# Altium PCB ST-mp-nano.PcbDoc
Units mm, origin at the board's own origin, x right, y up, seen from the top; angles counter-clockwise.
Board outline 18.67 x 47.4 mm, 2 copper layers (Top Layer, Bottom Layer); 49 components, 54 nets, 204 pads, 46 vias.
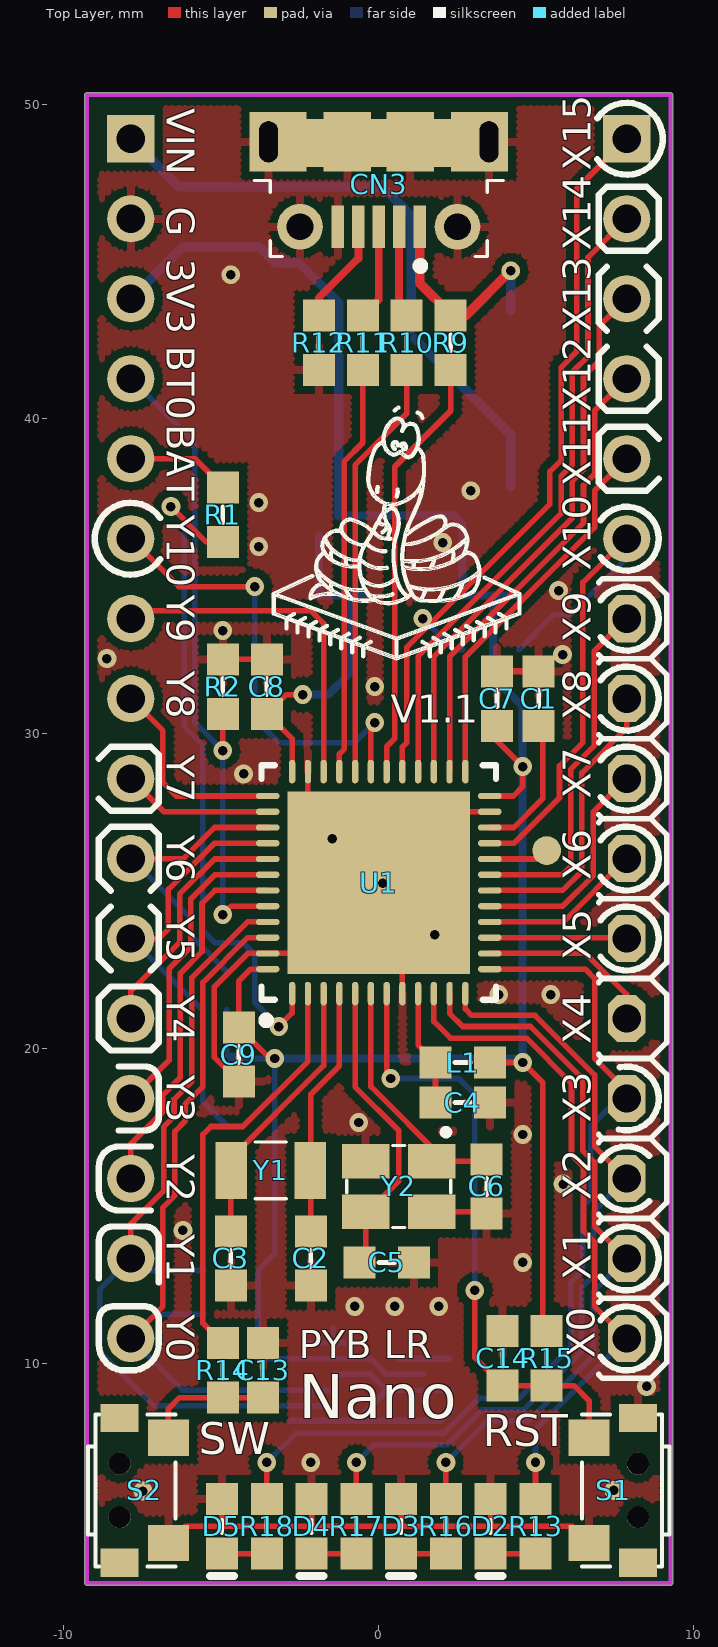
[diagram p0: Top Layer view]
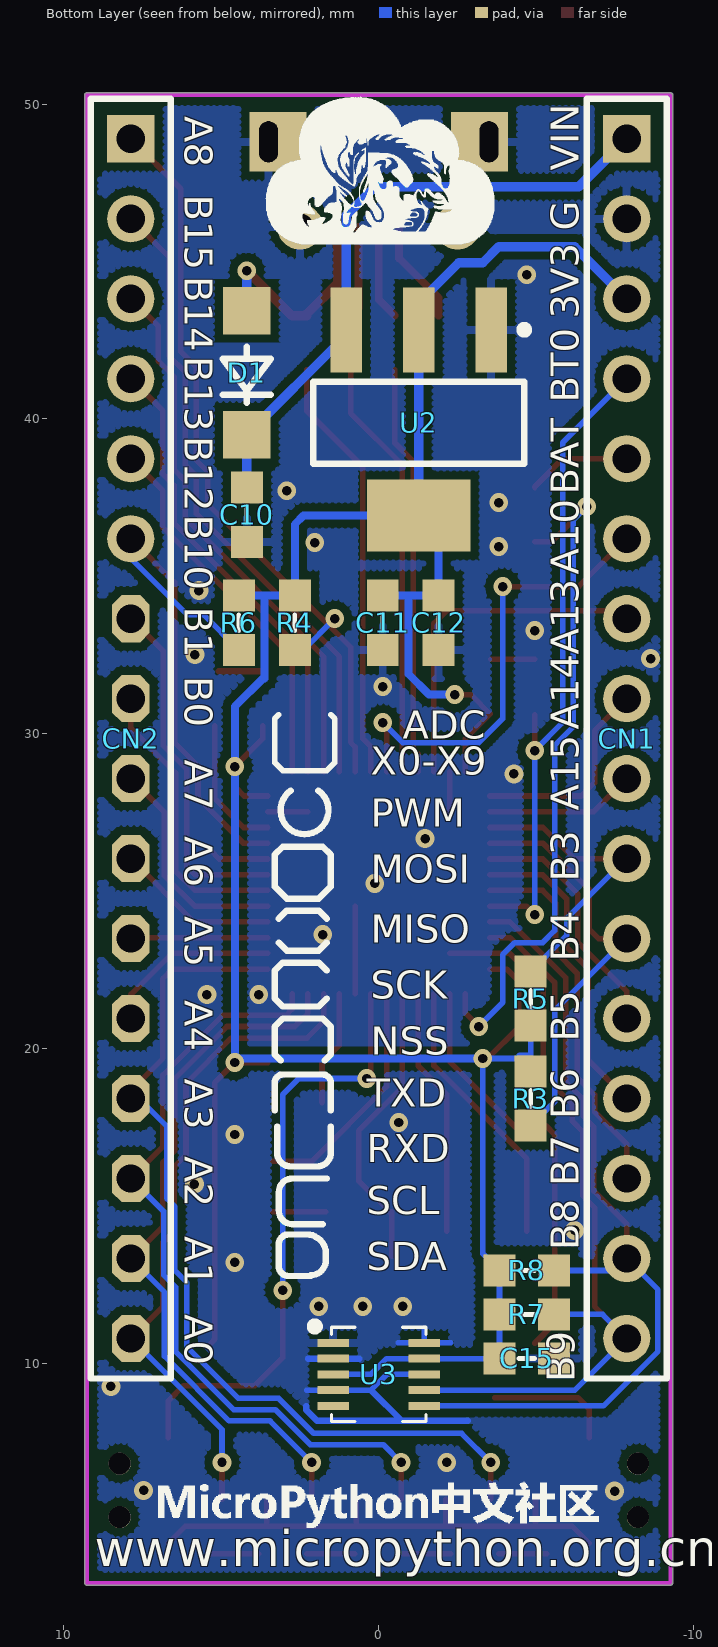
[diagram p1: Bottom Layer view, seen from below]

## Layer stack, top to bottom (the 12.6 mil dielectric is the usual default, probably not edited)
Top Layer: signal copper 0.0356
Dielectric: dielectric 0.32, FR-4, Dk 4.8
Bottom Layer: signal copper 0.0356

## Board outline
-9.335,3.023 ccw(c-9.271,3.023) -9.271,2.959 9.271,2.959 ccw(c9.271,3.023) 9.335,3.023 9.335,50.292 ccw(c9.271,50.292) 9.271,50.356 -9.271,50.356 ccw(c-9.271,50.292) -9.335,50.292

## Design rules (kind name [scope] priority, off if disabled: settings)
Clearance Clearance_polygon [InPolygon] p1: gap=0.254
Clearance [All] p2: gap=0.152
DiffPairsRouting [All] p1: maxlimit=0.254 minlimit=0.178 mostfreqgap=0.178 maxuncoupledlength=12.7
HoleSize [All] p1: absolutevalues=TRUE maxlimit=5.08 minlimit=0.025 maxpercent=80.000 minpercent=20.000
HoleToHoleClearance [All] p1: gap=0.178 allowstackedmicrovias=TRUE
MinimumSolderMaskSliver [All] p1: minsoldermaskwidth=0.178
PolygonConnect PolygonConnect_via [IsVia] p1: connectstyle=Direct reliefconductorwidth=0.254 reliefentries=4 polygonreliefangle="90 Angle"
PolygonConnect [All] p2: connectstyle=Relief reliefconductorwidth=0.254 reliefentries=4 polygonreliefangle="90 Angle"
RoutingVias [All] p1: holewidth=0.4 width=0.8 viastyle="Through Hole" minholewidth=0.3 minwidth=0.6 maxholewidth=0.711 maxwidth=1.27
SilkToSilkClearance [All] p1: silktosilkclearance=0.178
SilkscreenOverComponentPads [All] p1: minsilkscreentomaskgap=0.178
SolderMaskExpansion [All] p1: expansion=0.102
Width [All] p1: maxlimit=0.508 minlimit=0.178 preferedwidth=0.178
22 further rules are at their usual default settings.

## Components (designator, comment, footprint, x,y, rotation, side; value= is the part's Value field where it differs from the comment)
C1 "2u2" SMD0603 5.08,31.115 r90 top
C2 "2.2p" SMD0603 -2.159,13.335 r90 top
C3 "2.2p" SMD0603 -4.699,13.335 r90 top
C4 "104" SMD0603 2.667,18.288 r180 top
C5 "18p" SMD0603 0.254,13.208 r0 top
C6 "18p" SMD0603 3.429,15.621 r270 top
C7 "2u2" SMD0603 3.759,31.115 r90 top
C8 "104" SMD0603 -3.556,31.496 r270 top
C9 "104" SMD0603 -4.445,19.812 r90 top
C10 "2u2" SMD0603 4.191,36.957 r90 bottom
C11 "2u2" SMD0603 -0.127,33.528 r90 bottom
C12 "104" SMD0603 -1.905,33.528 r90 bottom
C13 "104" SMD0603 -3.683,9.779 r270 top
C14 "104" SMD0603 3.937,10.16 r270 top
C15 "104" SMD0603 -4.699,10.16 r0 bottom
CN1 "Header 16" HDR1X16#1 -7.874,48.895 r270 bottom
CN2 "Header 16" HDR1X16#2 7.874,48.895 r270 bottom
CN3 "1050170001" MOLEX_1050170001 0,46.101 r180 top locked
D1 "SS14" "SS24 - small" 4.191,43.434 r270 bottom
D2 "LED RED" LED0603 3.556,4.826 r90 top
D3 "LED GREEN" LED0603 0.711,4.826 r90 top
D4 "LED Yellow" LED0603 -2.134,4.826 r90 top
D5 "LED Blue" LED0603 -4.978,4.826 r90 top
L1 "1uH" SMD0603 2.667,19.558 r180 top
R1 "220" SMD0603 -4.953,36.957 r270 top
R2 "100k" SMD0603 -4.953,31.496 r90 top
R3 "10k" SMD0603 -4.826,18.415 r270 bottom
R4 "10k" SMD0603 2.667,33.528 r270 bottom
R5 "10k" SMD0603 -4.826,21.59 r90 bottom
R6 "10k" SMD0603 4.445,33.528 r270 bottom
R7 "10k" SMD0603 -4.699,11.557 r180 bottom
R8 "10k" SMD0603 -4.699,12.954 r180 bottom
R9 "560" SMD0603 2.286,42.418 r90 top
R10 "22R" SMD0603 0.889,42.418 r90 top
R11 "22R" SMD0603 -0.508,42.418 r90 top
R12 "100k" SMD0603 -1.905,42.418 r90 top
R13 "560" SMD0603 4.978,4.826 r270 top
R14 "10k" SMD0603 -4.953,9.779 r90 top
R15 "10k" SMD0603 5.334,10.16 r90 top
R16 "560" SMD0603 2.134,4.826 r270 top
R17 "560" SMD0603 -0.711,4.826 r270 top
R18 "560" SMD0603 -3.556,4.826 r270 top
S1 "SW-RST" SWPB_2X4_L 8.23,5.969 r270 top
S2 "" SWPB_2X4_L -8.23,5.969 r90 top
U1 "STM32F401CEU6" QFN48 0,25.273 r90 top
U2 "LM1117" SOT223 -1.27,39.878 r0 bottom
U3 "MMA7660FC" MMA7660 0,9.652 r180 bottom
Y1 "32K" TXC_9H03200019 -3.429,16.129 r180 top
Y2 "8M" SMD3225 0.635,15.621 r180 top

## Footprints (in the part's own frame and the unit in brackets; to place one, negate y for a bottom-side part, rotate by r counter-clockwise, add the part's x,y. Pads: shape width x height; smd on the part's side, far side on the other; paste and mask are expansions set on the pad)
HDR1X16#1 [mm] "Connector; Header; 16 Position"
  rect 1.5x1.5 hole 0.9: 1(0,0)
  round 1.5 hole 0.9: 2(2.54,0) 3(5.08,0) 4(7.62,0) 5(10.16,0) 6(12.7,0) 7(15.24,0) 8(17.78,0) 9(20.32,0) 10(22.86,0) 11(25.4,0) 12(27.94,0) 13(30.48,0) 14(33.02,0) 15(35.56,0) 16(38.1,0)
  silkscreen extent -1.27,-1.27 39.37,1.27
HDR1X16#2 [mm] "Connector; Header; 16 Position"
  rect 1.5x1.5 hole 0.9: 1(0,0)
  round 1.5 hole 0.9: 2(2.54,0) 3(5.08,0) 4(7.62,0) 5(10.16,0) 6(12.7,0)
  oct 1.5x1.2 hole 0.9: 7(15.24,0) 8(17.78,0) 9(20.32,0) 10(22.86,0) 11(25.4,0) 12(27.94,0) 13(30.48,0) 14(33.02,0) 15(35.56,0) 16(38.1,0)
  silkscreen extent -1.27,-1.27 39.37,1.27
LED0603 [mil]
  rect 40x40 smd: 1(-34,0) 2(34,0)
  silkscreen extent -62,-15 8,15
MMA7660 [mm]
  rect 1x0.25 smd: 1(-1.45,1) 2(-1.45,0.5) 3(-1.45,0) 4(-1.45,-0.5) 5(-1.45,-1) 6(1.45,-1) 7(1.45,-0.5) 8(1.45,0) 9(1.45,0.5) 10(1.45,1)
  silkscreen extent -2.16,-1.5 1.5,1.65, body extent -1.52,-1.52 1.52,1.52, height 0.9
MOLEX_1050170001 [mm] "USB Micro-B Connector"
  rect 0.4x1.35 smd: 1(-1.3,0) 2(-0.65,0) 3(0,0) 4(0.65,0) 5(1.3,0)
  round 1.45 hole 0.85: 6(-2.5,0) 11(2.5,0)
  rect 1.8x1.9 hole 0.6 slot 1.3 at 90 deg copper offset 0.3,0: 7(-3.5,-2.7)
  rect 1.5x1.9 smd: 8(-1,-2.7) 9(1,-2.7)
  rect 1.8x1.9 hole 0.6 slot 1.3 at 90 deg copper offset -0.3,0: 10(3.5,-2.7)
  silkscreen extent -3.95,-1.46 3.95,1.37, body extent -4.1,-5.21 4.1,0.19, height 2.58
QFN48 [mm] "QFN, 48-Leads, Body 7x7mm, Pitch 0.5mm, IPC Medium Density"
  oval 0.75x0.2 smd: 1(-3.525,2.75) 2(-3.525,2.25) 3(-3.525,1.75) 4(-3.525,1.25) 5(-3.525,0.75) 6(-3.525,0.25) 7(-3.525,-0.25) 8(-3.525,-0.75) 9(-3.525,-1.25) 10(-3.525,-1.75) 11(-3.525,-2.25) 12(-3.525,-2.75) 25(3.525,-2.75) 26(3.525,-2.25) 27(3.525,-1.75) 28(3.525,-1.25) 29(3.525,-0.75) 30(3.525,-0.25) 31(3.525,0.25) 32(3.525,0.75) 33(3.525,1.25) 34(3.525,1.75) 35(3.525,2.25) 36(3.525,2.75)
  oval 0.2x0.75 smd: 13(-2.75,-3.525) 14(-2.25,-3.525) 15(-1.75,-3.525) 16(-1.25,-3.525) 17(-0.75,-3.525) 18(-0.25,-3.525) 19(0.25,-3.525) 20(0.75,-3.525) 21(1.25,-3.525) 22(1.75,-3.525) 23(2.25,-3.525) 24(2.75,-3.525) 37(2.75,3.525) 38(2.25,3.525) 39(1.75,3.525) 40(1.25,3.525) 41(0.75,3.525) 42(0.25,3.525) 43(-0.25,3.525) 44(-0.75,3.525) 45(-1.25,3.525) 46(-1.75,3.525) 47(-2.25,3.525) 48(-2.75,3.525)
  rect 5.8x5.8 smd: 49(0,0)
  silkscreen extent -4.5,-3.72 3.72,3.73, body extent -3.57,-3.57 3.57,3.57, height 0.9
SMD0603 [mil]
  rect 40x40 smd: 1(-34,0) 2(34,0)
  silkscreen extent -10,0 10,0, body extent -40,-20 40,20, height 20
SMD3225 [mm] "Crystal SMD 3.2x2.5mm compatible with 2.5x2.0mm"
  rect 1.5x1.1 smd mask+0.05: 1(-1.05,-0.8) 2(1.05,-0.8) 3(1.05,0.8) 4(-1.05,0.8)
  silkscreen extent -1.65,-1.82 1.65,1.3, body extent -1.65,-1.3 1.65,1.3, height 1
SOT223 [mm] "SOT223, 4-Leads, Body 6.5x3.5mm, Pitch 2.3mm, Lead Span 7mm, IPC Low Density"
  rect 1x2.7 smd: 1(-2.3,-2.95) 2(0,-2.95) 3(2.3,-2.95)
  rect 3.3x2.294 smd: 4(0,2.95)
  silkscreen extent -3.47,-3.07 3.35,1.3, body extent -3.35,-1.85 3.35,1.85, height 1.7
"SS24 - small" [mm]
  rect 1.5x1.5 smd: 1(0,0) 2(3.937,0)
  silkscreen extent 1.14,-0.76 2.92,0.76, body extent -0.64,-0.89 4.57,0.89, height 3
SWPB_2X4_L [mm]
  rect 1.15x1.3 smd: 1(-1.675,-1.55) 2(1.675,-1.55)
  rect 0.9x1.2 smd: ""(-2.3,0) ""(2.3,0)
  round 0.7 hole 0.7: ""(-0.85,0) ""(0.85,0)
  silkscreen extent -2.41,-1.78 2.41,1
TXC_9H03200019 [mm]
  rect 1x1.8 smd: 1(-1.25,0) 2(1.25,0)
  silkscreen extent -0.5,-0.9 0.5,0.9, body extent -1.73,-0.85 1.73,0.85, height 0.8

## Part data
C1 C2 C3 C4 C5 C6 C7 C8 C9 C10 C11 C12 C13 C14 C15: library part Cap
CN1 CN2: "Header, 16-Pin"
D1: library part Diode
D2: library part LED-RED
D3: library part LED-GREEN
D4: library part LED-YELLOW
D5: library part LED-BLUE
L1: library part Inductor
R1 R2 R3 R4 R5 R6 R7 R8 R9 R10 R11 R12 R13 R14 R15 R16 R17 R18: library part Res
S1 S2: library part SW-PB, "Switch"
U3: library part MMA7660
Y1: library part XTAL
Y2: library part XTAL_SMD

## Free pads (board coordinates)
  rect 5.08x1.524 smd: 0(0.229,48.768)
  round 0.914 smd: 0(5.334,26.289)

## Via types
v1: diameter 0.6, hole 0.3, Top Layer to Bottom Layer, 46 vias

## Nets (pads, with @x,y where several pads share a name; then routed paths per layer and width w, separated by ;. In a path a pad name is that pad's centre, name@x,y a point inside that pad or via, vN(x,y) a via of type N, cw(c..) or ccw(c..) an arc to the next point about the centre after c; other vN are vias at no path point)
BOOT0: CN1.4 R2.1 U1.44 | length 20.9
  Top Layer w0.178: v1(-4.953,24.257) -4.687,24.523 U1.44 ; v1(-4.953,29.464) R2.1@-4.953,30.607
  Bottom Layer w0.178: CN1.4 -5.842,39.243 -5.842,30.353 v1(-4.953,29.464) v1(-4.953,24.257)
DM: CN3.2 R10.2 | length 2.9
  Top Layer w0.254: CN3.2 0.65,43.521 R10.2
DP: CN3.3 R11.2 | length 3
  Top Layer w0.254: R11.2 0,43.79 CN3.3
GND: C1.2 C2.1 C3.1 C4.1 C5.2 C6.2 C7.2 C8.1 C9.1 C10.1 C11.1 C12.1 C13.1 C14.1 C15.1 CN1.2 CN3.5 CN3.6 CN3.7 CN3.8 CN3.9 CN3.10 CN3.11 D2.2 D3.2 D4.2 D5.2 pad.0@0.229,48.768 R2.2 R12.1 S1.2 S1.@8.23,8.269 S2.1 U1.8 U1.23 U1.35 U1.47 U1.49 U2.1 U3.1 U3.2 U3.4 U3.8 U3.10 Y2.2 Y2.4 | length 48.2
  Top Layer w0.178: S2.1 -6.148,4.826 3.556,4.826 ; -4.978,4.851 D5.2 ; R2.2 C8.1 ; C9.1 -5.22,19.723 -5.22,21.963 -4.16,23.023 U1.47 U1.49@-2.25,23.023 ; U1.49@-2.25,27.523 U1.35 ; -2.134,4.851 D4.2 ; 0.711,4.877 D3.2 ; U1.8 U1.49@0.75,24.523 ; Y2.4 C6.2@3.365,14.821 ; U1.49@2.25,27.523 U1.23 ; D2.2 3.556,4.826 ; S1.2 6.148,4.826 3.556,4.826
  Top Layer w0.203: C7.2@3.683,31.979 C1.2
  Bottom Layer w0.178: -2.286,10.652 U3.10 ; U3.8 -0.254,9.652 0.246,9.152 U3.4 2.286,9.152 ; -1.45,11.109 U3.10 ; -0.614,10.652 U3.10
  Bottom Layer w0.203: -2.831,8.179 -0.727,8.179 ; 0.246,9.152 -0.727,8.179 ; 0.614,10.152 U3.2 2.247,10.152 ; 2.306,8.649 2.306,8.523 1.961,8.179 -0.727,8.179
  other v1: -7.493,5.944 7.468,5.969 -2.159,6.858 8.509,9.271 -0.762,11.811 0.508,11.811 1.905,11.811 4.572,13.208 -6.223,14.224 5.854,15.697 4.572,17.272 -0.635,17.653 3.81,21.717 5.461,21.717 1.778,23.622 0.127,25.248 -1.473,26.67 -4.293,28.727 -0.127,31.496 -8.636,32.385 5.842,32.512 -4.953,33.274 5.715,34.544 -3.81,35.941 2.032,36.068 -3.81,37.338 2.921,37.719 -4.699,44.577
ID: CN3.4 R12.2 | length 3.3
  Top Layer w0.254: R12.2 -1.905,43.845 -0.65,45.1 CN3.4
NetC1_1: C1.1 U1.22 | length 4.4
  Top Layer w0.178: U1.22 4.29,27.023 5.207,27.94 C1.1@5.207,30.251
NetC2_2: C2.2 U1.4 Y1.1 | length 7.9
  Top Layer w0.178: C2.2 -2.159,18.547 -1.25,19.456 U1.4
NetC3_2: C3.2 U1.3 Y1.2 | length 8.8
  Top Layer w0.178: C3.2 -4.699,16.51 -1.75,19.459 U1.3
NetC4_2: C4.2 L1.2 U1.9 | length 3.7
  Top Layer w0.178: U1.9 1.25,20.111 L1.2 C4.2
NetC5_1: C5.1 U1.5 Y2.3 | length 9.4
  Top Layer w0.178: U1.5 -0.75,18.784 0.635,17.399 0.635,15.794 -0.338,14.821 Y2.3 C5.1@-0.415,13.403
NetC6_1: C6.1 U1.6 Y2.1 | length 7.6
  Top Layer w0.178: U1.6 -0.25,18.792 2.121,16.421 C6.1@3.365,16.421
NetC13_2: C13.2 R14.1 S2.2 | length 4.1
  Top Layer w0.178: S2.2 -6.68,8.56 -6.325,8.915 C13.2
NetD2_1: D2.1 R13.2 | length 1.5
  Top Layer w0.178: D2.1@3.81,3.962 R13.2@5.334,3.962
NetD3_1: D3.1 R16.2 | length 1.5
  Top Layer w0.178: D3.1@0.762,3.962 R16.2@2.286,3.962
NetD4_1: D4.1 R17.2 | length 1.5
  Top Layer w0.178: D4.1@-2.286,3.962 R17.2@-0.762,3.962
NetD5_1: D5.1 R18.2 | length 1.5
  Top Layer w0.178: D5.1@-5.334,3.962 R18.2@-3.81,3.962
NetR1_2: R1.2 U1.1 | length 21.8
  Top Layer w0.178: v1(-6.604,37.211) -5.486,36.093 R1.2 ; v1(-3.175,20.701) -2.75,21.126 U1.1
  Bottom Layer w0.178: v1(-6.604,37.211) -6.172,36.779 -6.172,30.216 -5.588,29.632 -5.588,23.749 -5.207,23.368 -4.318,23.368 -3.937,22.987 -3.937,21.463 v1(-3.175,20.701)
NRST: C14.2 R15.1 S1.1 U1.7 | length 19.4
  Top Layer w0.178: U1.7 0.25,19.181 v1(0.381,19.05) ; v1(3.048,12.319) 3.048,10.185 C14.2 R15.1 6.198,9.296 6.68,8.814 S1.1
  Bottom Layer w0.178: v1(0.381,19.05) 2.54,19.05 3.048,18.542 v1(3.048,12.319)
PA0: CN2.16 R13.1 U1.10 | length 21.2
  Top Layer w0.178: U1.10 1.75,20.856 2.273,20.333 4.686,20.333 6.121,18.898 6.121,16.617 6.502,16.236 6.502,14.204 6.857,13.849 6.857,11.812 CN2.16 ; R13.1 v1(4.978,6.858)
  Bottom Layer w0.178: v1(4.978,6.858) 4.978,7.899 CN2.16
PA1: CN2.15 R16.1 U1.11 | length 22.8
  Top Layer w0.178: R16.1 v1(2.134,6.858) ; U1.11 2.25,21.118 2.667,20.701 4.821,20.701 6.477,19.045 6.477,16.764 6.857,16.384 6.857,14.352 CN2.15
  Bottom Layer w0.178: v1(2.134,6.858) 3.454,8.179 4.755,8.179 6.807,10.231 6.807,12.268 CN2.15
PA2-TX2: CN2.14 R17.1 U1.12 | length 25.1
  Top Layer w0.178: R17.1 v1(-0.711,6.858) ; U1.12 2.75,21.253 2.946,21.057 4.968,21.057 6.858,19.167 6.858,18.837 ; 6.857,18.836 6.857,16.892 CN2.14
  Bottom Layer w0.178: v1(-0.711,6.858) -0.145,7.425 2.177,7.425 3.286,8.534 4.608,8.534 6.452,10.378 6.452,12.426 6.833,12.807 6.833,14.834 CN2.14
PA3-RX2: CN2.13 R18.1 U1.13 | length 28.8
  Top Layer w0.178: R18.1 v1(-3.556,6.858) ; U1.13 6.56,22.523 6.857,22.226 6.857,19.686 7.874,18.669 CN2.13
  Bottom Layer w0.178: v1(-3.556,6.858) -2.634,7.78 2.065,7.78 3.175,8.89 4.46,8.89 6.096,10.526 6.096,12.573 6.477,12.954 6.477,14.986 6.731,15.24 6.731,17.526 7.62,18.415 CN2.13
PA4-NSS1: CN2.12 U1.14 | length 5.7
  Top Layer w0.178: U1.14 6.568,23.023 7.874,21.717 CN2.12
PA5-SCK1: CN2.11 U1.15 | length 4.3
  Top Layer w0.178: U1.15 CN2.11@7.846,23.523
PA6-MISO1: CN2.10 U1.16 | length 5.2
  Top Layer w0.178: U1.16 5.862,24.023 CN2.10
PA7-MOSI1: CN2.9 U1.17 | length 7.2
  Top Layer w0.178: U1.17 5.844,24.523 6.807,25.486 6.807,27.508 CN2.9
PA8-SCL3: CN2.1 R4.2 U1.29 | length 24.7
  Top Layer w0.178: U1.29 0.75,29.579 0.894,29.723 0.894,32.751 5.435,37.291 5.435,38.328 5.79,38.683 5.79,41.635 6.289,42.134 6.289,47.31 CN2.1
  Bottom Layer w0.178: v1(1.397,33.655) 2.388,32.664 R4.2
PA9-VSUB: R9.1 U1.30 | length 13.6
  Top Layer w0.178: U1.30 0.25,29.587 0.508,29.845 0.508,38.481 2.286,40.259 R9.1
PA10: CN1.6 U1.31 | length 14.8
  Top Layer w0.178: CN1.6 -6.35,34.671 v1(-3.937,34.671) ; U1.31 -0.25,30.23 v1(-0.127,30.353)
  Bottom Layer w0.178: v1(-3.937,34.671) -3.937,30.48 -3.175,29.718 -0.762,29.718 v1(-0.127,30.353)
PA11-DM: R10.1 U1.32 | length 13.4
  Top Layer w0.178: U1.32 -0.75,38.534 0.889,40.173 R10.1
PA12-DP: R11.1 U1.33 | length 13.1
  Top Layer w0.178: U1.33 -1.25,29.357 -1.091,29.516 -1.091,38.66 -0.508,39.243 R11.1
PA13: CN1.7 U1.34 | length 11.1
  Top Layer w0.178: CN1.7 -7.62,33.909 -2.159,33.909 -1.75,33.5 U1.34
PA14: CN1.8 U1.37 | length 6.6
  Top Layer w0.178: CN1.8 -6.857,30.098 -6.857,28.447 -6.433,28.023 U1.37
PA15-NSS3: CN1.9 U1.38 | length 4.8
  Top Layer w0.178: CN1.9 -6.822,27.523 U1.38
PB0: CN2.8 U1.18 | length 9.3
  Top Layer w0.178: U1.18 5.841,25.023 6.452,25.634 6.452,28.759 7.874,30.181 CN2.8
PB1: CN2.7 U1.19 | length 11.3
  Top Layer w0.178: U1.19 5.838,25.523 6.096,25.781 6.096,28.87 6.84,29.614 6.84,32.621 CN2.7
PB2: pad.0@5.334,26.289 U1.20 | length 1.9
  Top Layer w0.178: U1.20 5.068,26.023 pad.0@5.334,26.289
PB3-SDA2: CN1.10 R5.2 U1.39 | length 9.6
  Top Layer w0.178: CN1.10 -6.203,26.035 -5.215,27.023 U1.39
  Bottom Layer w0.178: CN1.10 -5.969,24.13 -5.969,23.597 R5.2
PB4-SDA3: CN1.11 R3.2 U1.40 | length 13.5
  Top Layer w0.178: CN1.11 -6.985,23.495 -6.68,23.8 -6.68,25.054 -5.212,26.523 U1.40
  Bottom Layer w0.178: CN1.11 -5.588,21.209 -5.588,18.313 R3.2
PB5: CN1.12 U1.41 | length 7.9
  Top Layer w0.178: CN1.12 -7.874,21.824 -6.325,23.373 -6.325,24.907 -5.209,26.023 U1.41
PB6-TX1: CN1.13 U1.42 | length 9.9
  Top Layer w0.178: CN1.13 -6.655,19.634 -6.655,22.54 -5.969,23.226 -5.969,24.76 -5.206,25.523 U1.42
PB7-RX1: CN1.14 U1.43 | length 11.9
  Top Layer w0.178: CN1.14 -7.874,16.977 -6.857,17.994 -6.857,18.532 -6.299,19.091 -6.299,22.393 -5.613,23.078 -5.613,24.613 -5.203,25.023 U1.43
PB8-SCL1: CN1.15 R8.2 U1.45 U3.6 | length 26.8
  Top Layer w0.178: CN1.15 -7.874,14.437 -6.833,15.479 -6.833,17.516 -6.502,17.847 -6.502,18.385 -5.944,18.943 -5.944,22.245 -4.166,24.023 U1.45
  Bottom Layer w0.178: R8.2 -7.493,12.954 CN1.15 -8.865,12.344 -8.865,10.384 -7.133,8.652 U3.6
PB9-SDA1: CN1.16 R7.2 U1.46 U3.7 | length 24.6
  Top Layer w0.178: CN1.16 -6.858,11.811 -6.858,12.912 ; -6.857,12.913 -6.857,14.951 -6.477,15.331 -6.477,17.368 -6.146,17.699 -6.146,18.238 -5.588,18.796 -5.588,22.098 -4.163,23.523 U1.46
  Bottom Layer w0.178: R7.2 -7.112,11.557 CN1.16 -6.231,9.152 U3.7
PB10-SCL2: CN2.6 R6.2 U1.21 | length 17.2
  Top Layer w0.178: U1.21 4.298,26.523 5.74,27.965 5.74,28.981 6.485,29.726 6.485,34.806 CN2.6
  Bottom Layer w0.178: R6.2 5.563,33.782 6.096,33.782 7.874,35.56 CN2.6
PB12-NSS1: CN2.5 U1.25 | length 12.1
  Top Layer w0.178: U1.25 2.75,32.444 6.857,36.551 6.857,37.718 CN2.5
PB13-SCK1: CN2.4 U1.26 | length 14.8
  Top Layer w0.178: U1.26 2.25,32.447 6.502,36.698 6.502,37.886 6.857,38.242 6.857,40.258 CN2.4
PB14-MISO1: CN2.3 U1.27 | length 17.6
  Top Layer w0.178: U1.27 1.75,32.45 6.146,36.846 6.146,38.033 6.502,38.389 6.502,41.341 7,41.839 7,42.941 CN2.3
PB15-MOSI1: CN2.2 U1.28 | length 20.3
  Top Layer w0.178: U1.28 1.25,32.453 5.79,36.993 5.79,38.181 6.146,38.536 6.146,41.488 6.645,41.986 6.645,45.126 CN2.2
PC13-SW: R14.2 U1.2 | length 13.3
  Top Layer w0.178: R14.2 -5.588,11.278 -5.588,17.272 -5.334,17.526 -4.318,17.526 -2.25,19.594 U1.2
VBAT: CN1.5 R1.1 | length 3.3
  Top Layer w0.178: CN1.5 -5.842,38.735 -4.953,37.846 R1.1
VBUS: CN3.1 D1.1 R9.2 | length 7
  Top Layer w0.305: CN3.1 1.3,44.318 2.286,43.332 R9.2 2.769,43.282 v1(4.191,44.704)
  Bottom Layer w0.305: D1.1 v1(4.191,44.704)
VCC: C7.1 C8.2 C9.2 C11.2 C12.2 C15.2 CN1.3 L1.1 R3.1 R4.1 R5.1 R6.1 R7.1 R8.1 R15.2 U1.24 U1.36 U1.48 U2.2 U2.4 U3.3 U3.9 | length 93.4
  Top Layer w0.178: U1.48 -4.064,22.523 -4.445,22.142 C9.2 -3.454,19.685 v1(-3.302,19.685) ; U1.36 -2.75,29.845 -3.537,30.632 -2.928,31.242 v1(-2.413,31.242) ; U1.24 4.274,28.023 4.572,28.321 v1(4.572,28.956) 3.683,29.845 C7.1@3.683,30.251 ; L1.1 v1(4.572,19.558) 5.207,18.923 5.207,10.77 R15.2@5.334,10.643
  Bottom Layer w0.178: -4.826,21.234 -4.826,19.787 -4.47,19.787 ; R3.1@-4.724,19.685 v1(-3.302,19.685) -3.302,13.487 R8.1 R7.1 C15.2 ; C15.2@-3.827,10.152 U3.9 -0.246,10.152 0.254,9.652 U3.3
  Bottom Layer w0.254: v1(-3.302,19.685) v1@4.445,19.685 ; v1@-2.413,31.281 v1(-2.413,31.242) -1.6,31.242 -0.94,31.902 -0.94,34.392 ; U2.4@-1.905,36.293 C12.2 C11.2@-0.381,34.392 ; U2.4 2.391,36.928 2.667,36.652 R4.1 3.632,34.392 ; 3.632,31.75 3.632,31.801 ; R6.1 3.632,34.392 ; v1(4.572,19.558) v1(4.572,28.956) 4.572,30.861 3.632,31.801 ; 3.632,31.801 3.632,34.392
  Bottom Layer w0.305: CN1.3 -6.223,45.466 -3.81,45.466 -3.302,44.958 -2.54,44.958 -1.27,43.688 U2.2 U2.4
VIN: C10.2 CN1.1 D1.2 U2.3 | length 19.5
  Bottom Layer w0.305: CN1.1 -6.35,47.371 0.127,47.371 1.03,46.468 U2.3 ; U2.3@1.143,42.545 D1.2 C10.2@4.191,37.846
pads on no net: S1.@8.23,3.669 S1.@8.23,5.119 S1.@8.23,6.819 S2. U3.5

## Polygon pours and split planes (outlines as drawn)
GND on Bottom Layer "Bottom Layer" (hatched 90Degree grid 0.203 track 0.203, remove dead copper, pour order 2): 9.271,50.292 -9.271,50.292 -9.271,3.023 9.271,3.023
GND on Top Layer "Top Layer-No Net" (hatched 90Degree grid 0.203 track 0.203, remove dead copper, pour order 5): -9.271,3.023 9.271,3.023 9.271,50.292 -9.271,50.292

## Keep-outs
Keep-Out Layer:
  lines w0.127: -9.271,3.023 9.271,3.023 9.271,50.292 -9.271,50.292 -9.271,3.023

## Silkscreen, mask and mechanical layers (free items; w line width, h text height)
Top Overlay:
  drawing of 770 lines, arcs and shapes, not listed
  text "VIN" at -6.731,49.873 h0.89 r270
  text "X15" at 6.731,47.879 h0.89 r90
  text "G" at -6.731,46.736 h0.89 r270
  text "X14" at 6.731,45.339 h0.89 r90
  text "3V3" at -6.731,45.085 h0.89 r270
  text "X13" at 6.731,42.748 h0.89 r90
  text "BT0" at -6.731,42.316 h0.89 r270
  text "X12" at 6.731,40.208 h0.89 r90
  text "BAT" at -6.731,39.827 h0.89 r270
  text "X11" at 6.731,37.846 h0.89 r90
  text "Y10" at -6.731,36.957 h0.89 r270
  text "X10" at 6.731,35.179 h0.89 r90
  text "Y9" at -6.731,34.417 h0.89 r270
  text "X9" at 6.731,32.893 h0.89 r90
  text "Y8" at -6.731,32.004 h0.89 r270
  text "X8" at 6.731,30.429 h0.89 r90
  text "V1.1" at 0.381,30.353 h0.89
  text "Y7" at -6.731,29.337 h0.89 r270
  text "X7" at 6.731,27.94 h0.89 r90
  text "Y6" at -6.731,26.797 h0.89 r270
  text "X6" at 6.731,25.349 h0.89 r90
  text "Y5" at -6.731,24.257 h0.89 r270
  text "X5" at 6.731,22.809 h0.89 r90
  text "Y4" at -6.731,21.717 h0.89 r270
  text "X4" at 6.731,20.142 h0.89 r90
  text "Y3" at -6.731,19.177 h0.89 r270
  text "X3" at 6.731,17.653 h0.89 r90
  text "Y2" at -6.731,16.637 h0.89 r270
  text "X2" at 6.731,15.189 h0.89 r90
  text "Y1" at -6.731,14.097 h0.89 r270
  text "X1" at 6.731,12.649 h0.89 r90
  text "Y0" at -6.731,11.557 h0.89 r270
  text "PYB LR" at -2.54,10.16 h0.89
  text "X0" at 6.858,10.16 h0.89 r90
  text "Nano" at -2.54,8.255 h1.4
  text "RST" at 3.302,7.366 h1.02
  text "SW" at -5.715,7.112 h1.02
Bottom Overlay:
  drawing of 3912 lines, arcs and shapes, not listed
  text "A8" at 6.159,49.606 h0.89 r90
  text "VIN" at -6.35,47.879 h0.89 r270
  text "B15" at 6.159,47.117 h0.89 r90
  text "G" at -6.35,45.974 h0.89 r270
  text "B14" at 6.159,44.526 h0.89 r90
  text "3V3" at -6.35,43.18 h0.89 r270
  text "B13" at 6.159,41.986 h0.89 r90
  text "BT0" at -6.35,40.513 h0.89 r270
  text "B12" at 6.159,39.446 h0.89 r90
  text "BAT" at -6.35,37.592 h0.89 r270
  text "B10" at 6.159,36.957 h0.89 r90
  text "A10" at -6.35,35.052 h0.89 r270
  text "B1" at 6.159,34.036 h0.89 r90
  text "A13" at -6.35,32.512 h0.89 r270
  text "B0" at 6.159,31.826 h0.89 r90
  text "A14" at -6.35,30.124 h0.89 r270
  text "ADC" at -0.762,29.845 h0.89
  text "A7" at 6.159,29.175 h0.89 r90
  text "X0-X9" at 0.254,28.702 h0.89
  text "A15" at -6.35,27.559 h0.89 r270
  text "PWM" at 0.254,27.051 h0.89
  text "A6" at 6.159,26.746 h0.89 r90
  text "B3" at -6.35,25.298 h0.89 r270
  text "MOSI" at 0.254,25.273 h0.89
  text "A5" at 6.159,24.206 h0.89 r90
  text "MISO" at 0.254,23.368 h0.89
  text "B4" at -6.35,22.758 h0.89 r270
  text "SCK" at 0.254,21.59 h0.89
  text "A4" at 6.159,21.539 h0.89 r90
  text "B5" at -6.35,20.218 h0.89 r270
  text "NSS" at 0.254,19.812 h0.89
  text "A3" at 6.159,19.05 h0.89 r90
  text "TXD" at 0.381,18.161 h0.89
  text "B6" at -6.35,17.755 h0.89 r270
  text "A2" at 6.159,16.586 h0.89 r90
  text "RXD" at 0.381,16.383 h0.89
  text "B7" at -6.35,15.621 h0.89 r270
  text "SCL" at 0.381,14.732 h0.89
  text "A1" at 6.159,14.046 h0.89 r90
  text "B8" at -6.35,13.589 h0.89 r270
  text "SDA" at 0.381,12.954 h0.89
  text "A0" at 6.159,11.557 h0.89 r90
  text "B9" at -6.223,9.398 h0.89 r270
  text "www.micropython.org.cn" at 9.017,3.556 h1.14
Mechanical 1:
  lines w0.127: -9.271,3.009 9.271,3.009 9.271,50.278 -9.271,50.278 -9.271,3.009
